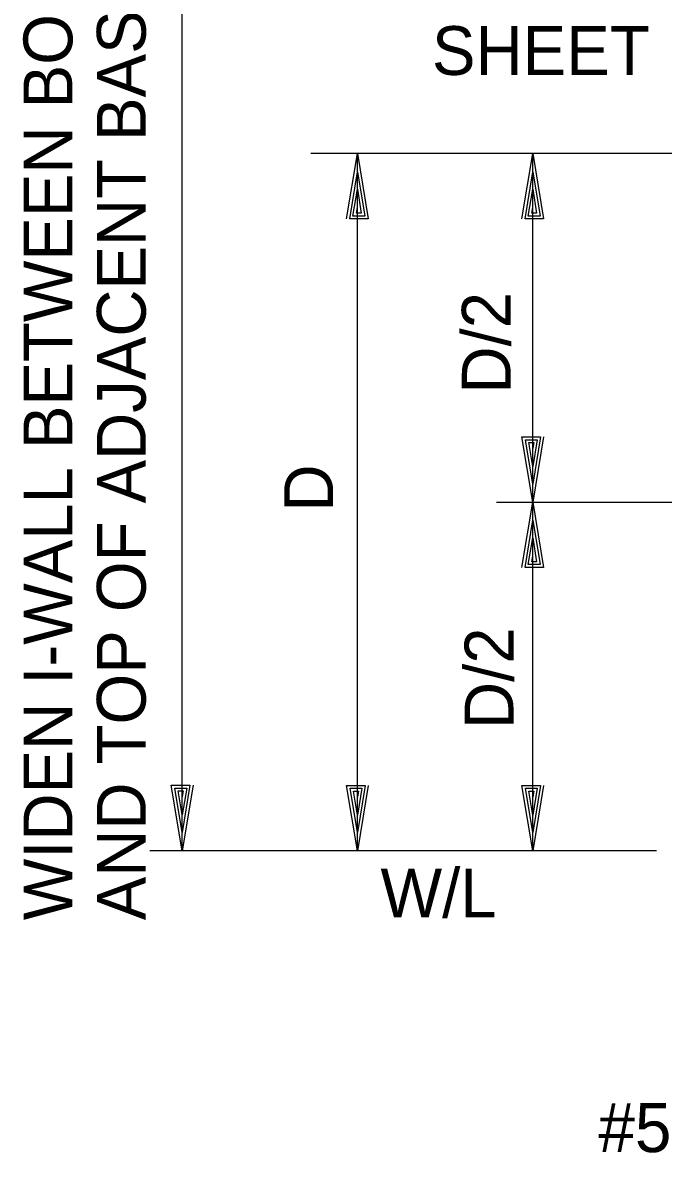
# Model space of a CAD drawing. Extents: x 22369.6 to 22428.3, y 22369.6 to 22415.
# Drawn here: x 22403.75 to 22406.186, y 22376.472 to 22380.805 of the extents above; entities that cross this region are included whole.
import ezdxf

# ---------------------------------------------------------------- set-up
doc = ezdxf.new("R2010")
doc.units = 0
doc.layers.add('Level 1', color=7, linetype='Continuous')
doc.layers.add('Level 4', color=7, linetype='Continuous')

msp = doc.modelspace()

# ---------------------------------------------------------------- linework, layer by layer
at = {"layer": 'Level 1'}
for p, q in [((22404.3565, 22377.6536), (22404.3565, 22381.6336)), ((22406.2282, 22380.307), (22404.8457, 22380.307)), ((22405.0232, 22377.6536), (22405.0232, 22380.307)), ((22405.6899, 22378.9803), (22405.6899, 22380.307)), ((22405.5525, 22378.9803), (22411.9528, 22378.9803)), ((22405.6899, 22377.6536), (22405.6899, 22378.9803)), ((22405.6899, 22378.9803), (22405.6899, 22378.9803)), ((22405.6899, 22378.9113), (22405.6899, 22378.9113)), ((22404.3565, 22377.7229), (22404.3565, 22377.7229)), ((22405.6899, 22377.7226), (22405.6899, 22377.7226)), ((22406.1598, 22377.6536), (22404.234, 22377.6536)), ((22404.3565, 22377.6536), (22404.3565, 22377.6536)), ((22405.6899, 22377.6536), (22405.6899, 22377.6536))]:
    msp.add_line(p, q, dxfattribs=at)
for points in [[(22404.9821, 22380.0589), (22405.0232, 22380.307), (22405.0643, 22380.0589), (22404.994, 22380.0589), (22405.0232, 22380.238), (22405.0511, 22380.0695), (22405.0059, 22380.0695), (22405.0232, 22380.1716), (22405.0378, 22380.0801), (22405.0192, 22380.0801), (22405.0232, 22380.1027)], [(22405.6487, 22380.0589), (22405.6899, 22380.307), (22405.731, 22380.0589), (22405.6607, 22380.0589), (22405.6899, 22380.238), (22405.7177, 22380.0695), (22405.6726, 22380.0695), (22405.6899, 22380.1716), (22405.7044, 22380.0801), (22405.6859, 22380.0801), (22405.6899, 22380.1027)], [(22405.731, 22379.2284), (22405.6899, 22378.9803), (22405.6487, 22379.2284), (22405.7191, 22379.2284), (22405.6899, 22379.0493), (22405.662, 22379.2178), (22405.7071, 22379.2178), (22405.6899, 22379.1156), (22405.6753, 22379.2071), (22405.6938, 22379.2071), (22405.6899, 22379.1846)], [(22405.6487, 22378.7322), (22405.6899, 22378.9803), (22405.731, 22378.7322), (22405.6607, 22378.7322), (22405.6899, 22378.9113), (22405.7177, 22378.7428), (22405.6726, 22378.7428), (22405.6899, 22378.845), (22405.7044, 22378.7534), (22405.6859, 22378.7534), (22405.6899, 22378.776)], [(22404.3979, 22377.9029), (22404.3565, 22377.6536), (22404.3152, 22377.9029), (22404.3859, 22377.9029), (22404.3565, 22377.7229), (22404.3285, 22377.8923), (22404.3739, 22377.8923), (22404.3565, 22377.7896), (22404.3419, 22377.8816), (22404.3605, 22377.8816), (22404.3565, 22377.8589)], [(22405.0643, 22377.9017), (22405.0232, 22377.6536), (22404.9821, 22377.9017), (22405.0524, 22377.9017), (22405.0232, 22377.7226), (22404.9953, 22377.8911), (22405.0404, 22377.8911), (22405.0232, 22377.7889), (22405.0086, 22377.8805), (22405.0272, 22377.8805), (22405.0232, 22377.8579)], [(22405.731, 22377.9017), (22405.6899, 22377.6536), (22405.6487, 22377.9017), (22405.7191, 22377.9017), (22405.6899, 22377.7226), (22405.662, 22377.8911), (22405.7071, 22377.8911), (22405.6899, 22377.7889), (22405.6753, 22377.8805), (22405.6938, 22377.8805), (22405.6899, 22377.8579)]]:
    msp.add_lwpolyline(points, dxfattribs=at)

# ---------------------------------------------------------------- texts
at = {"layer": 'Level 4'}
for s, height, p in [('AND TOP OF ADJACENT BASE SLAB', 0.185698, (22404.2179, 22377.389)), ('WIDEN I-WALL BETWEEN BOTTOM', 0.185698, (22403.9389, 22377.389)), ('D/2', 0.18573, (22405.6058, 22379.3938)), ('D', 0.1857, (22404.9303, 22378.9447)), ('D/2', 0.18573, (22405.6166, 22378.1169))]:
    msp.add_text(s, height=height, rotation=90, dxfattribs=at).set_placement(p)
for s, height, p in [('SHEET PILING', 0.185729, (22405.3064, 22380.6064)), ('W/L', 0.18573, (22405.1108, 22377.3995)), ("#5, 5'-0'' LONG EF", 0.186667, (22405.9395, 22376.5064))]:
    msp.add_text(s, height=height, dxfattribs=at).set_placement(p)

doc.saveas('drawing.dxf')
